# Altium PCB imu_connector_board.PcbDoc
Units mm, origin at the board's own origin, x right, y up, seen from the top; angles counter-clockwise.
Board outline 40.39 x 23.88 mm, 2 copper layers (Top Layer, Bottom Layer); 6 components, 8 nets, 21 pads, 0 vias.
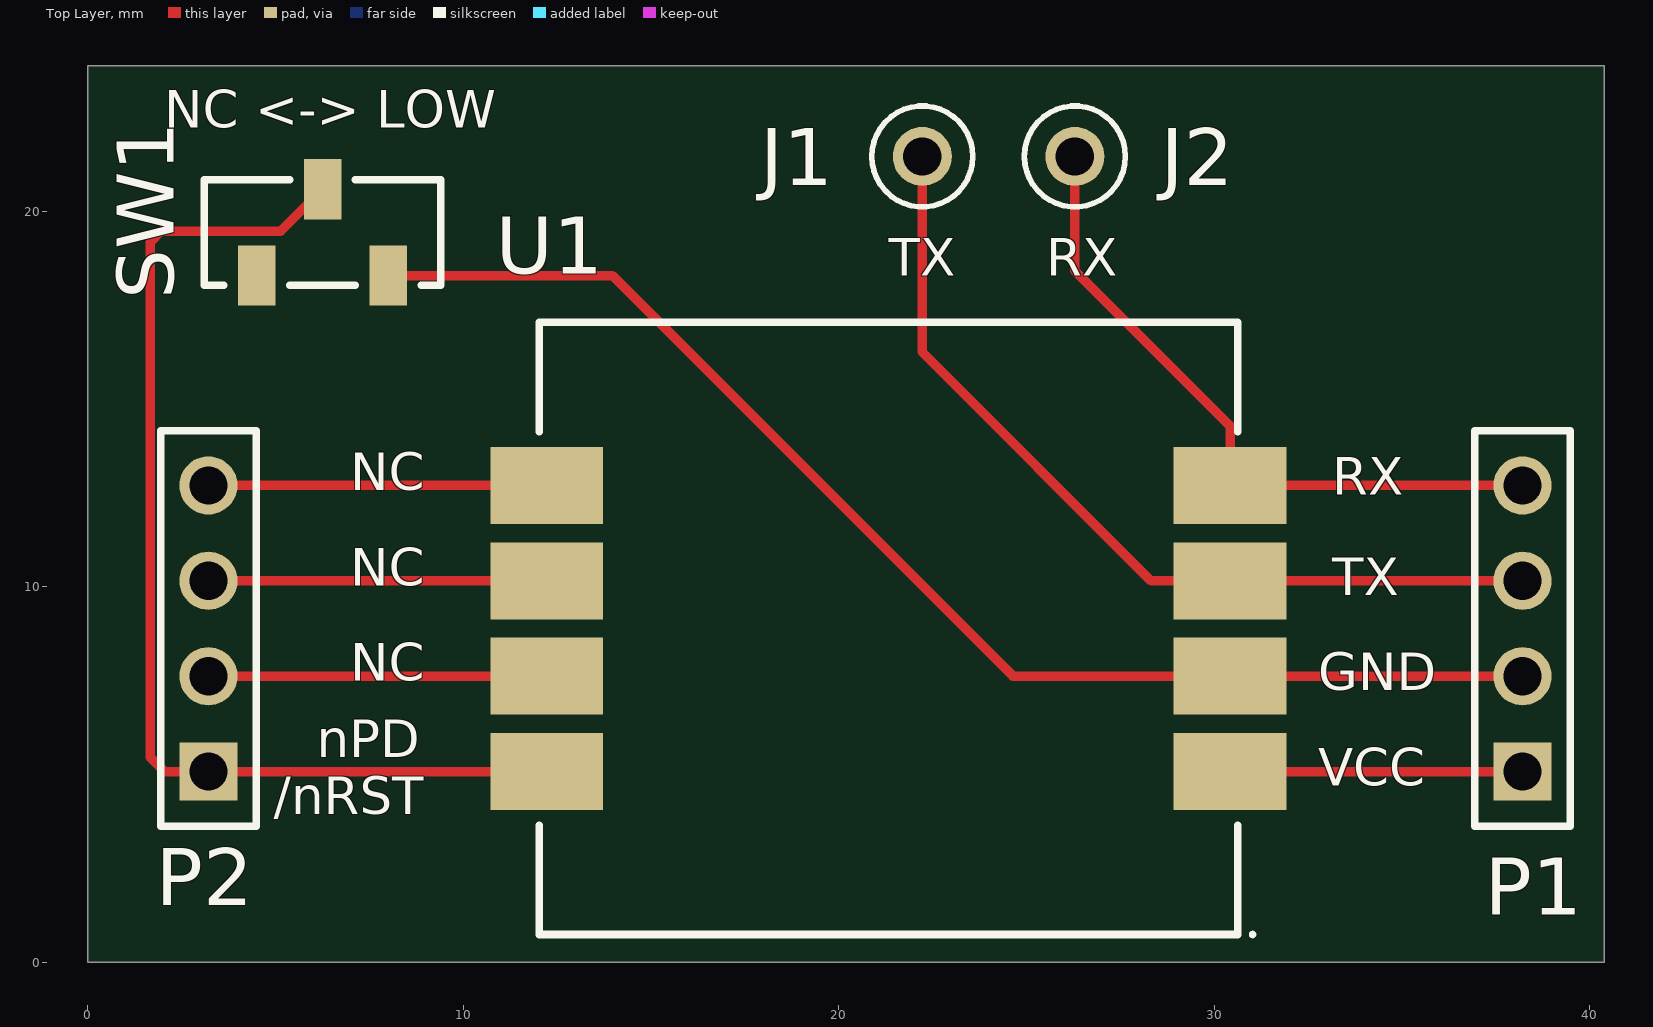
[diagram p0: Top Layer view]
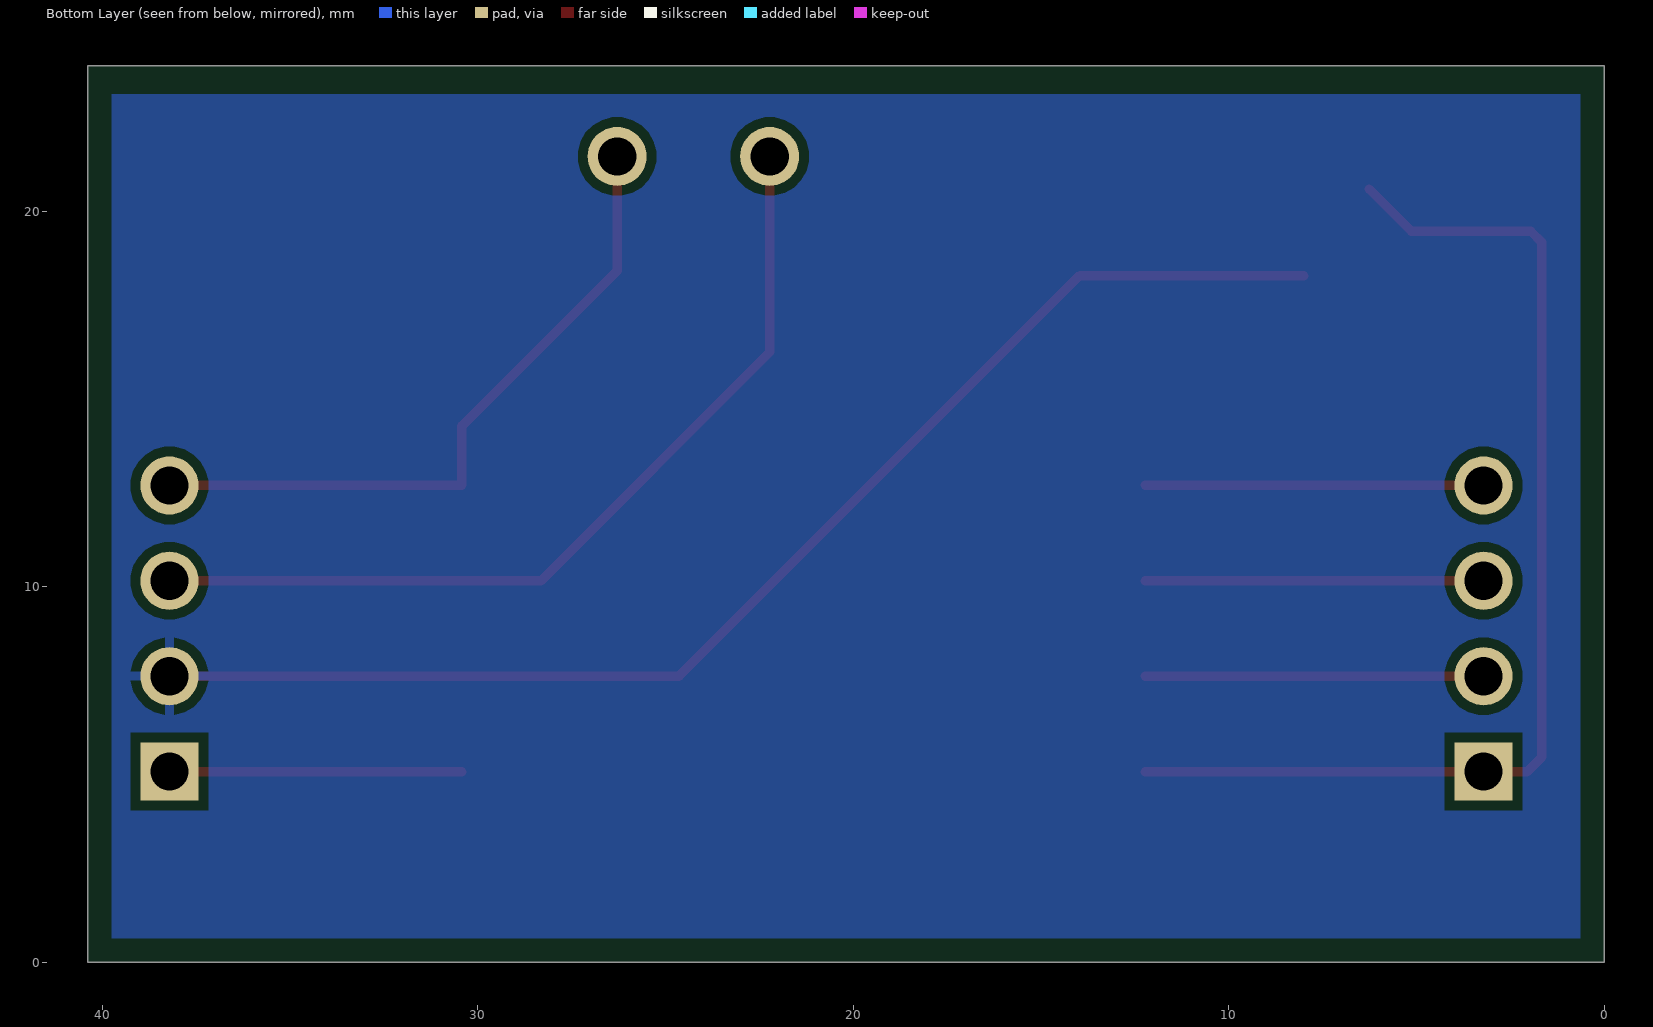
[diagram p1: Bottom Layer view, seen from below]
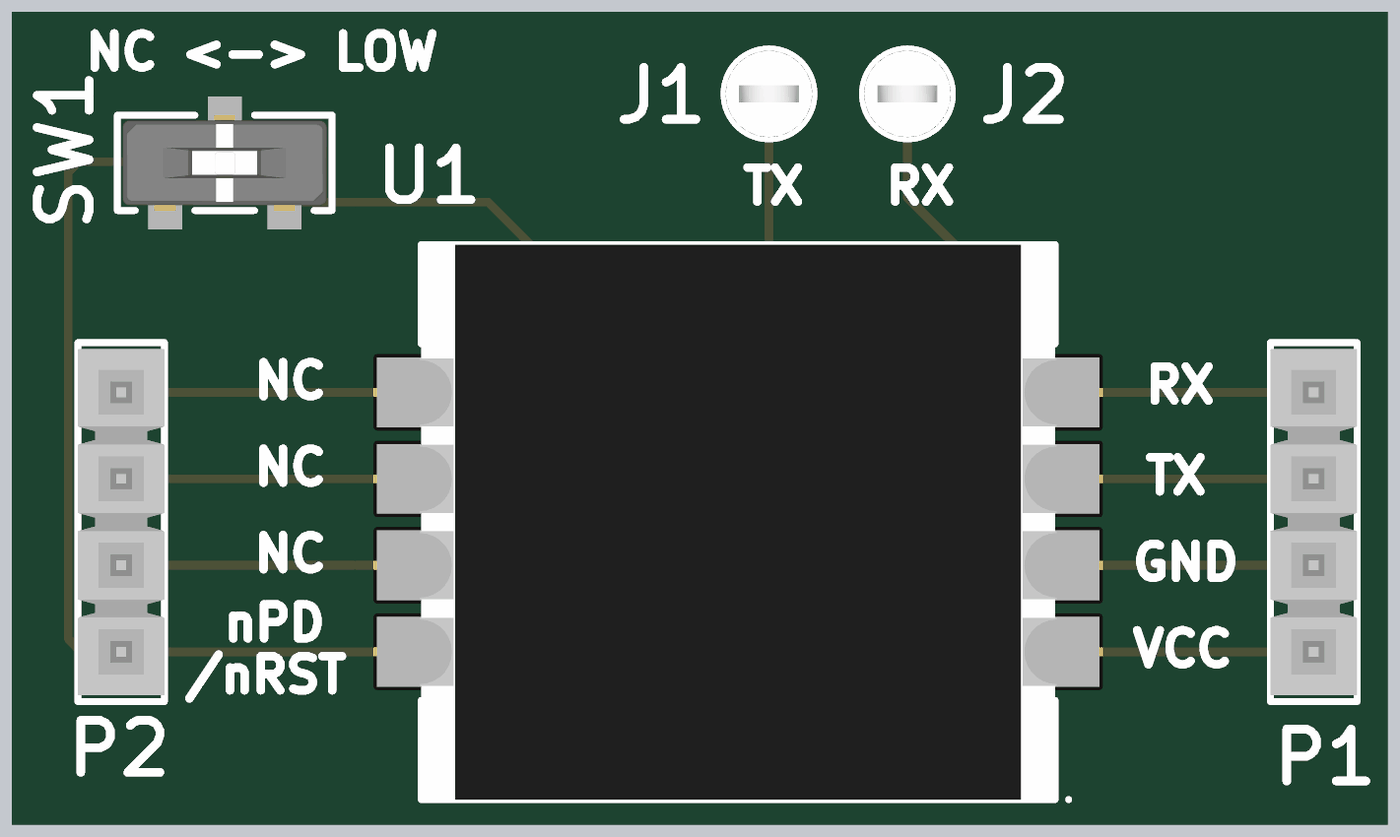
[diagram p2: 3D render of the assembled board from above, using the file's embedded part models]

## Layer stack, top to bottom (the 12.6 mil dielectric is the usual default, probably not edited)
Top Solder: solder mask 0.0102, Solder Resist, Dk 3.5
Top Layer: signal copper 0.0356
Dielectric 1: dielectric 0.32, FR-4, Dk 4.8
Bottom Layer: signal copper 0.0356
Bottom Solder: solder mask 0.0102, Solder Resist, Dk 3.5

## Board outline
0,0 40.386,0 40.386,23.876 0,23.876

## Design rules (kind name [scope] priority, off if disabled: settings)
Clearance [All] p1: gap=0.254 ignorepadtopadclearanceinfootprint=FALSE
PolygonConnect [All] p1: connectstyle=Relief reliefconductorwidth=0.254 reliefentries=4 polygonreliefangle="90 Angle" airgapwidth=0.254
RoutingVias [All] p1: holewidth=0.711 width=1.27 viastyle="Through Hole" minholewidth=0.711 minwidth=1.27 maxholewidth=0.711 maxwidth=1.27
SolderMaskExpansion [All] p1: expansion=0.102 istentingtop=FALSE
SupplyNets "Schematic Supply Nets_1" [InNet('VCC')] p1: voltage=0.000
SupplyNets "Schematic Supply Nets" [InNet('GND')] p2: voltage=0.000
Width [All] p1: maxlimit=0.254 minlimit=0.254 preferedwidth=0.254
30 further rules are at their usual default settings.

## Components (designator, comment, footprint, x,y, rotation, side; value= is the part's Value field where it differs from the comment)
J1 "5002" FP-5002-MFG 22.225,21.463 r0 top
J2 "5002" FP-5002-MFG 26.289,21.463 r0 top
P1 "TSW-104-08-L-S" SMTC-TSW-104-08-X-S 38.212,5.08 r90 top
P2 "TSW-104-08-L-S" SMTC-TSW-104-08-X-S 3.212,5.08 r90 top
SW1 "CJS-1201TA" FP-CJS-1201TA-MFG 6.251,19.438 r0 top
U1 "EBIMU-9DOFV6" EBIMU-9DOFV6 21.321,8.89 r180 top

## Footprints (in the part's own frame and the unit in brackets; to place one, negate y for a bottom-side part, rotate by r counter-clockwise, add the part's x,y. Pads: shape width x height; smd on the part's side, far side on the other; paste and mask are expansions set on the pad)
EBIMU-9DOFV6 [mm] "Chip Array, Concave, 8-Leads, Pitch 2.54mm,  Body 16.30x18.60mm,  IPC Low Density"
  rect 3x2.05 smd: 1(-9.1,3.81) 2(-9.1,1.27) 3(-9.1,-1.27) 4(-9.1,-3.81) 5(9.1,3.81) 6(9.1,1.27) 7(9.1,-1.27) 8(9.1,-3.81)
  silkscreen extent -9.75,-8.15 9.3,8.2, body extent -9.35,-8.15 9.35,8.15, height 3.1
FP-5002-MFG [mm]
  round 1.57 hole 1.02 paste-2539.97 mask+0: 1(0,0)
  silkscreen extent -1.35,-1.34 1.35,1.34, body extent -1.45,-1.45 1.45,1.45, height 0.25
FP-CJS-1201TA-MFG [mm]
  rect 1x1.6 smd paste+0 mask+0: 1(-1.75,-1.15) 2(0,1.15) 3(1.75,-1.15)
  silkscreen extent -3.15,-1.4 3.15,1.4, body extent -3.25,-2.05 3.25,2.05, height 0.25
SMTC-TSW-104-08-X-S [mm] ".025 SQ Post Terminal Strip Assembly, 1x4 Pins, Vertical, 2.54mm Pitch, Male"
  rect 1.55x1.55 hole 1.02: 1(0,0)
  round 1.55 hole 1.02: 2(2.54,0) 3(5.08,0) 4(7.62,0)
  silkscreen extent -1.46,-1.27 9.08,1.27, body extent -1.27,-1.27 8.89,1.27, height 8.38

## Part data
J1 J2: library part CMP-2000-05182-2, "PC TEST POINT MINIATURE WHITE", Color=White, Flammability Rating="UL94 V-0", Package Quantity=100
P1 P2: library part CMP-1024-00358-1, "0.025\" SQ Post Header, Through-hole, Vertical, -55 to 125 degC, 2.54 mm Pitch, 4-Pin, Male, RoHS", Manufacturer=Samtec, Temperature Range="-55 to 125 degC"
SW1: library part CMP-71745-000001-1, "SWITCH SLIDE SPDT 100MA 6V", Contact Current Rating=100mA, Contact Resistance=100mΩ, Manufacturer="Copal Electronics Inc", Operating Force=5.9N, Temperature="-40°C to +85°C", Temperature Range High=+85°C, Temperature Range Low=-40°C, Voltage Rating Dc=6V
U1: library part CMP-00000-2

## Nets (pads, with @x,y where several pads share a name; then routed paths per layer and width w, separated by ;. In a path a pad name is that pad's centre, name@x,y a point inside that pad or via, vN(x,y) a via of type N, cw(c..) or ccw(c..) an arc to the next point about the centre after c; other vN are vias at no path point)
GND: P1.2 SW1.3 U1.2 | length 34.6
  Top Layer w0.254: SW1.3 13.97,18.288 24.638,7.62 U1.2 P1.2
NetJ1_1: J1.1 P1.3 U1.3 | length 23.7
  Top Layer w0.254: J1.1 22.225,16.256 28.321,10.16 U1.3 P1.3
NetJ2_1: J2.1 P1.4 U1.4 | length 18.3
  Top Layer w0.254: J2.1 26.289,18.415 30.421,14.283 U1.4 P1.4
NetP2_2: P2.2 U1.6 | length 8.9
  Top Layer w0.254: P2.2@3.302,7.62 U1.6
NetP2_3: P2.3 U1.7 | length 8.9
  Top Layer w0.254: P2.3@3.302,10.16 U1.7
NetP2_4: P2.4 U1.8 | length 8.9
  Top Layer w0.254: P2.4@3.302,12.7 U1.8
nPD/nRST: P2.1 SW1.2 U1.5 | length 29.5
  Top Layer w0.254: P2.1 2.043,5.08 1.659,5.464 1.659,19.172 1.956,19.469 5.132,19.469 SW1.2 ; P2.1@3.302,5.08 U1.5
VCC: P1.1 U1.1 | length 7.8
  Top Layer w0.254: U1.1 P1.1
pads on no net: SW1.1

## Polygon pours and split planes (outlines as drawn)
GND on Bottom Layer "GND_L02_P000" (solid, pour order 0): 0.635,0.635 0.635,23.114 39.751,23.114 39.751,0.635

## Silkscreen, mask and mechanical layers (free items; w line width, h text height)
Top Overlay:
  text "NC <-> LOW" at 2.032,22.225 h1
  text "TX" at 21.336,18.288 h1
  text "RX" at 25.527,18.288 h1
  text "NC" at 6.985,12.573 h1
  text "RX" at 33.147,12.446 h1
  text "NC" at 6.985,10.033 h1
  text "TX" at 33.147,9.779 h1
  text "NC" at 6.985,7.493 h1
  text "GND" at 32.766,7.239 h1
  text "nPD" at 6.096,5.461 h1
  text "VCC" at 32.766,4.699 h1
  text "/nRST" at 4.953,3.937 h1

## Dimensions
3.212,12.7 to 38.212,5.08 on Mechanical 1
